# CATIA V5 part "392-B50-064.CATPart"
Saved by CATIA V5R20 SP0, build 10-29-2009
Part number: 392-B50-064
Definition: NONE
Nomenclature: 392-B50-064
Source: Unknown
Description: 392-B50-064
Bounding box of the stored display mesh (mm): x 0 to 64, y -24.564 to 24.564, z -24.4 to 24.222
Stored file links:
  C:\Users\Utente\Desktop\IO LAVORO\3D X SITO CF\X SITO\3D files 392B\392-B50-064.CATPart
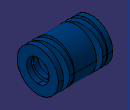
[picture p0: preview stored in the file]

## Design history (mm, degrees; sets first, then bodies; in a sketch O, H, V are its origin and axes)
Body1 "392-B50-064" (main body)
  Solid1: solid without history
